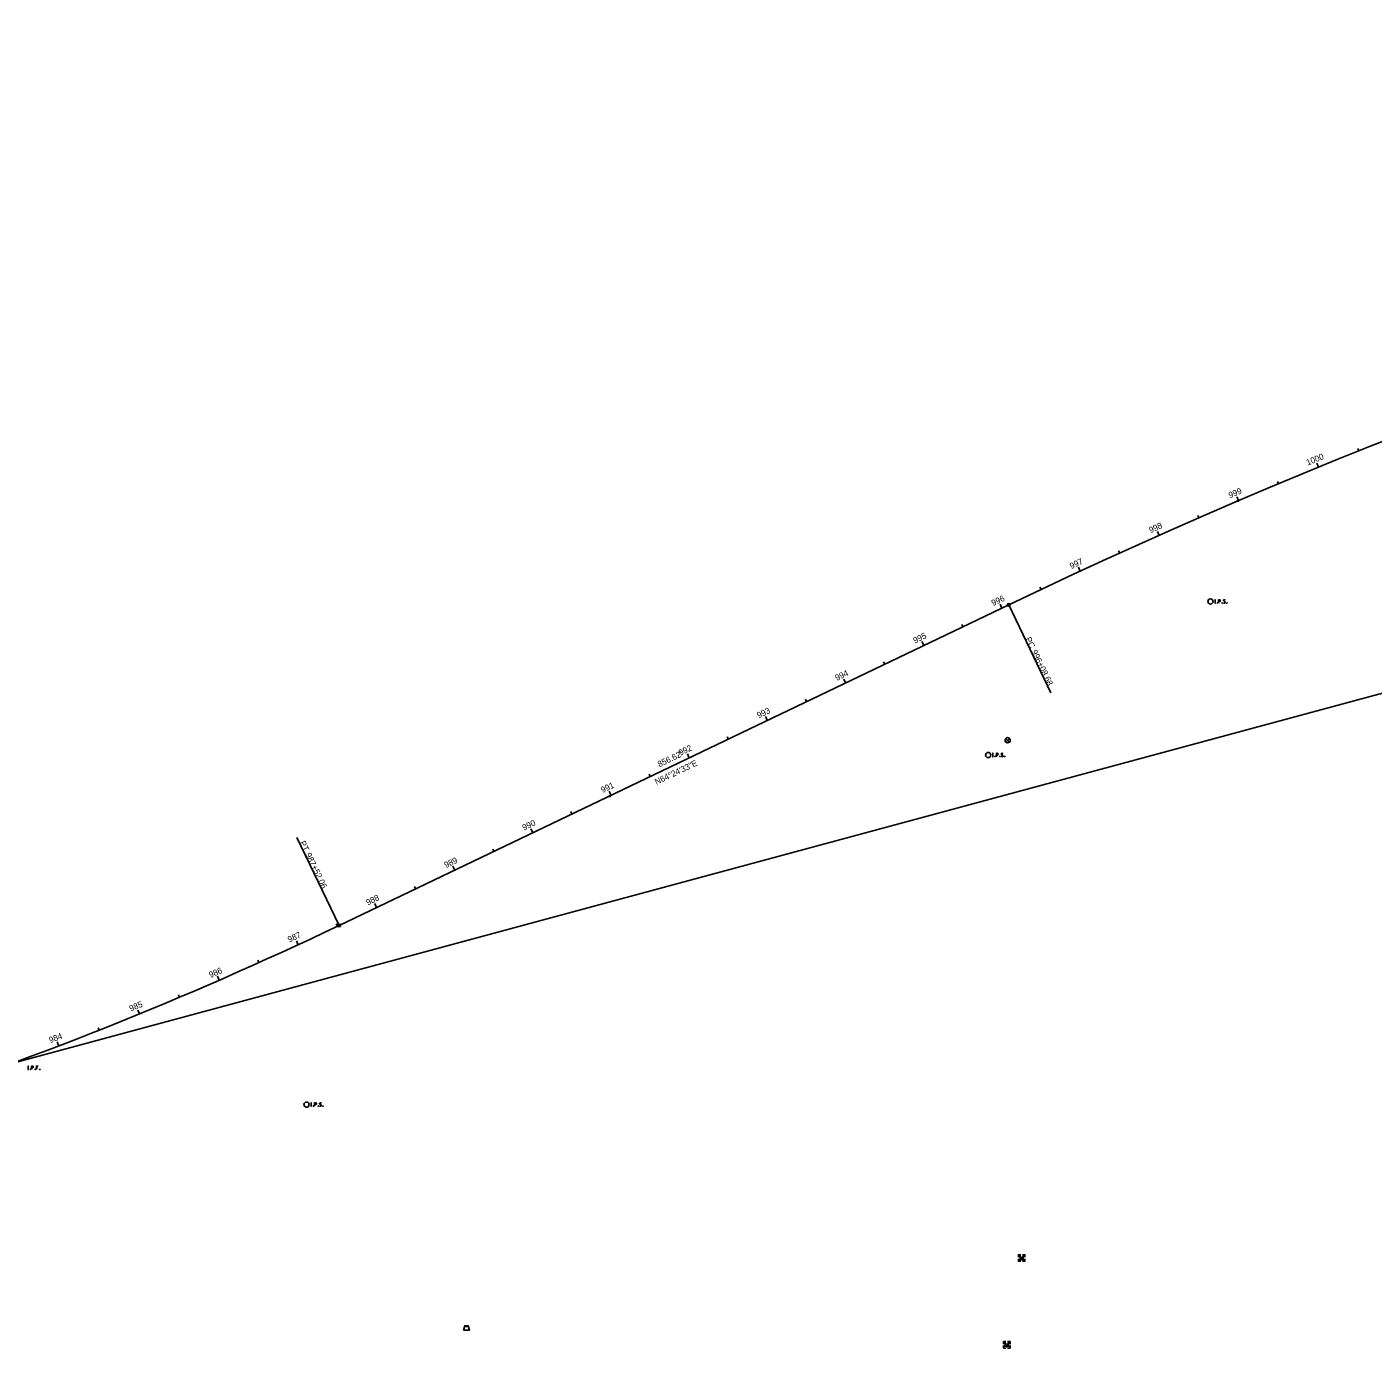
# Model space of a CAD drawing. Extents: x 2192033 to 2198234, y 657975 to 662607.
# Drawn here: x 2193587 to 2195140, y 660228 to 661753 of the extents above; entities that cross this region are included whole.
import ezdxf

# ---------------------------------------------------------------- set-up
doc = ezdxf.new("R2010")
doc.units = 0
for name, color, linetype in [('BR_P_Gen_Approach_Slab', 7, 'Continuous'), ('GE_X_Alignment_1000_Stations', 7, 'Continuous'), ('GE_X_Alignment_100_Stations', 7, 'Continuous'), ('GE_X_Alignment_500_Stations', 7, 'Continuous'), ('RD_P_Text', 7, 'Continuous'), ('SH_Border', 7, 'Continuous'), ('SH_Cut_Line', 7, 'Continuous'), ('SH_Data', 7, 'Continuous'), ('SH_Named_Boundary', 7, 'Continuous')]:
    doc.layers.add(name, color=color, linetype=linetype)

msp = doc.modelspace()

# ---------------------------------------------------------------- linework, layer by layer
at = {"layer": 'BR_P_Gen_Approach_Slab'}
for points in [[(2194957.2, 661091.7), (2194958.1, 661091.7)], [(2194957.7, 661087.7), (2194957.7, 661091.7)], [(2194961.6, 661087.7), (2194961.6, 661091.7), (2194962.9, 661091.7), (2194963, 661091.7), (2194963.2, 661091.6), (2194963.3, 661091.6), (2194963.4, 661091.5), (2194963.5, 661091.4), (2194963.6, 661091.2), (2194963.6, 661091), (2194963.6, 661090.6), (2194963.6, 661090.4), (2194963.6, 661090.3), (2194963.5, 661090), (2194963.3, 661089.9), (2194963.3, 661089.9), (2194963.1, 661089.8), (2194962.9, 661089.8), (2194961.6, 661089.8)], [(2194969.1, 661091.5), (2194969, 661091.5), (2194969, 661091.6), (2194968.7, 661091.7), (2194968.4, 661091.7), (2194968.2, 661091.7), (2194968.1, 661091.7), (2194967.8, 661091.6), (2194967.4, 661091.5), (2194967.3, 661091.2), (2194967.2, 661091), (2194967.2, 661090.8), (2194967.3, 661090.5), (2194967.5, 661090.3), (2194969, 661089.3), (2194969.1, 661089.2), (2194969.2, 661089.1), (2194969.2, 661088.9), (2194969.2, 661088.7), (2194969.2, 661088.5), (2194969.2, 661088.4), (2194969.1, 661088.2), (2194969.1, 661088.1), (2194969, 661088), (2194968.9, 661087.9), (2194968.9, 661087.9), (2194968.7, 661087.8), (2194968.7, 661087.8), (2194968.4, 661087.7), (2194968, 661087.7), (2194967.8, 661087.8), (2194967.4, 661088), (2194967.2, 661088.2)], [(2194957.2, 661087.7), (2194958.1, 661087.7)], [(2194960.1, 661088.3), (2194960.2, 661088.3), (2194960.3, 661088.2), (2194960.4, 661088.1), (2194960.4, 661087.9), (2194960.3, 661087.8), (2194960.2, 661087.7), (2194960.1, 661087.7), (2194960, 661087.8), (2194959.9, 661087.9), (2194959.9, 661088.1), (2194960, 661088.2), (2194960.1, 661088.3)], [(2194965.7, 661088.3), (2194965.8, 661088.3), (2194965.9, 661088.2), (2194966, 661088.1), (2194966, 661087.9), (2194965.9, 661087.8), (2194965.8, 661087.7), (2194965.7, 661087.7), (2194965.6, 661087.8), (2194965.5, 661087.9), (2194965.5, 661088.1), (2194965.6, 661088.2), (2194965.7, 661088.3)], [(2194971.1, 661088.3), (2194971.3, 661088.3), (2194971.4, 661088.2), (2194971.4, 661088.1), (2194971.4, 661087.9), (2194971.4, 661087.8), (2194971.3, 661087.7), (2194971.1, 661087.7), (2194971.1, 661087.8), (2194971, 661087.9), (2194971, 661088.1), (2194971.1, 661088.2), (2194971.1, 661088.3)], [(2194700.8, 660914.5), (2194701.7, 660914.5)], [(2194700.8, 660910.5), (2194701.7, 660910.5)], [(2194701.3, 660910.5), (2194701.3, 660914.5)], [(2194703.7, 660911), (2194703.8, 660911), (2194703.9, 660911), (2194704, 660910.8), (2194704, 660910.7), (2194703.9, 660910.6), (2194703.8, 660910.5), (2194703.7, 660910.5), (2194703.6, 660910.6), (2194703.5, 660910.7), (2194703.5, 660910.8), (2194703.6, 660911), (2194703.7, 660911)], [(2194705.2, 660910.5), (2194705.2, 660914.5), (2194706.5, 660914.5), (2194706.7, 660914.5), (2194706.9, 660914.4), (2194706.9, 660914.3), (2194707, 660914.3), (2194707.1, 660914.1), (2194707.2, 660914), (2194707.3, 660913.7), (2194707.3, 660913.3), (2194707.2, 660913.2), (2194707.2, 660913), (2194707.1, 660912.8), (2194707, 660912.7), (2194706.9, 660912.6), (2194706.7, 660912.6), (2194706.5, 660912.5), (2194705.2, 660912.5)], [(2194709.3, 660911), (2194709.4, 660911), (2194709.5, 660911), (2194709.6, 660910.8), (2194709.6, 660910.7), (2194709.5, 660910.6), (2194709.4, 660910.5), (2194709.3, 660910.5), (2194709.2, 660910.6), (2194709.1, 660910.7), (2194709.1, 660910.8), (2194709.2, 660911), (2194709.3, 660911)], [(2194712.7, 660914.2), (2194712.7, 660914.3), (2194712.6, 660914.3), (2194712.3, 660914.4), (2194712, 660914.5), (2194711.8, 660914.5), (2194711.7, 660914.5), (2194711.4, 660914.4), (2194711.1, 660914.2), (2194710.9, 660914), (2194710.8, 660913.7), (2194710.8, 660913.5), (2194710.9, 660913.3), (2194711.1, 660913), (2194712.6, 660912.1), (2194712.8, 660912), (2194712.8, 660911.9), (2194712.9, 660911.7), (2194712.9, 660911.5), (2194712.8, 660911.3), (2194712.8, 660911.2), (2194712.8, 660911), (2194712.7, 660910.9), (2194712.6, 660910.8), (2194712.6, 660910.7), (2194712.5, 660910.6), (2194712.4, 660910.6), (2194712.3, 660910.5), (2194712, 660910.5), (2194711.6, 660910.5), (2194711.4, 660910.6), (2194711, 660910.8), (2194710.8, 660911)], [(2194714.8, 660911), (2194714.9, 660911), (2194715, 660911), (2194715.1, 660910.8), (2194715.1, 660910.7), (2194715, 660910.6), (2194714.9, 660910.5), (2194714.8, 660910.5), (2194714.7, 660910.6), (2194714.6, 660910.7), (2194714.6, 660910.8), (2194714.7, 660911), (2194714.8, 660911)], [(2193914.4, 660511.1), (2193915.2, 660511.1)], [(2193914.4, 660507.1), (2193915.2, 660507.1)], [(2193914.8, 660507.1), (2193914.8, 660511.1)], [(2193917.2, 660507.6), (2193917.3, 660507.6), (2193917.4, 660507.5), (2193917.5, 660507.4), (2193917.5, 660507.2), (2193917.4, 660507.1), (2193917.3, 660507.1), (2193917.2, 660507.1), (2193917.1, 660507.1), (2193917, 660507.2), (2193917, 660507.4), (2193917.1, 660507.5), (2193917.2, 660507.6)], [(2193918.7, 660507.1), (2193918.7, 660511.1), (2193920, 660511.1), (2193920.2, 660511), (2193920.4, 660511), (2193920.5, 660510.9), (2193920.5, 660510.8), (2193920.6, 660510.7), (2193920.7, 660510.5), (2193920.8, 660510.3), (2193920.8, 660509.9), (2193920.8, 660509.8), (2193920.7, 660509.6), (2193920.6, 660509.4), (2193920.5, 660509.3), (2193920.4, 660509.2), (2193920.3, 660509.1), (2193920, 660509.1), (2193918.7, 660509.1)], [(2193922.8, 660507.6), (2193923, 660507.6), (2193923, 660507.5), (2193923.1, 660507.4), (2193923.1, 660507.2), (2193923, 660507.1), (2193923, 660507.1), (2193922.8, 660507.1), (2193922.7, 660507.1), (2193922.7, 660507.2), (2193922.7, 660507.4), (2193922.7, 660507.5), (2193922.8, 660507.6)], [(2193926.2, 660510.8), (2193926.2, 660510.8), (2193926.1, 660510.9), (2193925.9, 660511), (2193925.6, 660511.1), (2193925.3, 660511.1), (2193925.3, 660511.1), (2193924.9, 660511), (2193924.6, 660510.8), (2193924.4, 660510.5), (2193924.3, 660510.3), (2193924.3, 660510.1), (2193924.4, 660509.8), (2193924.6, 660509.6), (2193926.1, 660508.7), (2193926.3, 660508.5), (2193926.3, 660508.4), (2193926.4, 660508.2), (2193926.4, 660508), (2193926.4, 660507.8), (2193926.3, 660507.7), (2193926.3, 660507.6), (2193926.2, 660507.4), (2193926.2, 660507.3), (2193926.1, 660507.2), (2193926, 660507.2), (2193925.9, 660507.1), (2193925.8, 660507.1), (2193925.6, 660507.1), (2193925.2, 660507.1), (2193924.9, 660507.1), (2193924.6, 660507.3), (2193924.3, 660507.5)], [(2193928.3, 660507.6), (2193928.4, 660507.6), (2193928.5, 660507.5), (2193928.6, 660507.4), (2193928.6, 660507.2), (2193928.5, 660507.1), (2193928.4, 660507.1), (2193928.3, 660507.1), (2193928.2, 660507.1), (2193928.1, 660507.2), (2193928.1, 660507.4), (2193928.2, 660507.5), (2193928.3, 660507.6)]]:
    msp.add_lwpolyline(points, dxfattribs=at)
for centre in [(2194952.2, 661089.7), (2194695.8, 660912.5), (2193909.3, 660509)]:
    msp.add_circle(centre, 3, dxfattribs=at)
at = {"layer": 'GE_X_Alignment_1000_Stations'}
for p, q in [((2195077, 661244.7), (2195075.1, 661249.3)), ((2194719.5, 661085.8), (2194768.1, 660984.4)), ((2194621.4, 661038.9), (2194620.2, 661041.6)), ((2194170.5, 660822.9), (2194168.3, 660827.4)), ((2193946.9, 660715.8), (2193898.3, 660817.3)), ((2193716.5, 660613.6), (2193715.4, 660616.4))]:
    msp.add_line(p, q, dxfattribs=at)
for centre in [(2194719.5, 661085.8), (2193946.9, 660715.8)]:
    msp.add_circle(centre, 1.5, dxfattribs=at)
at = {"layer": 'GE_X_Alignment_100_Stations'}
for p, q in [((2195123.3, 661263.5), (2195122.2, 661266.3)), ((2195077, 661244.7), (2195075.1, 661249.3)), ((2195030.8, 661225.5), (2195029.7, 661228.3)), ((2194984.8, 661206), (2194982.8, 661210.6)), ((2194938.9, 661186.2), (2194937.7, 661189)), ((2194893.1, 661166), (2194891.1, 661170.6)), ((2194847.5, 661145.5), (2194846.3, 661148.3)), ((2194802.1, 661124.7), (2194800, 661129.3)), ((2194756.8, 661103.6), (2194755.5, 661106.3)), ((2194711.6, 661082.1), (2194709.5, 661086.6)), ((2194719.5, 661085.8), (2194768.1, 660984.4)), ((2194666.5, 661060.5), (2194665.2, 661063.2)), ((2194621.4, 661038.9), (2194619.3, 661043.4)), ((2194576.4, 661017.3), (2194575.1, 661020)), ((2194531.3, 660995.7), (2194529.1, 661000.2)), ((2194486.2, 660974.1), (2194484.9, 660976.8)), ((2194441.1, 660952.5), (2194438.9, 660957)), ((2194396, 660930.9), (2194394.7, 660933.6)), ((2194350.9, 660909.3), (2194348.7, 660913.8)), ((2194305.8, 660887.7), (2194304.5, 660890.4)), ((2194260.7, 660866.1), (2194258.5, 660870.6)), ((2194215.6, 660844.5), (2194214.3, 660847.2)), ((2194170.5, 660822.9), (2194168.3, 660827.4)), ((2193946.9, 660715.8), (2193898.3, 660817.3)), ((2194125.4, 660801.3), (2194124.1, 660804)), ((2194080.3, 660779.7), (2194078.1, 660784.2)), ((2194035.2, 660758.1), (2194033.9, 660760.8)), ((2193990.1, 660736.5), (2193988, 660741)), ((2193945, 660714.9), (2193943.7, 660717.6)), ((2193899.8, 660693.6), (2193897.7, 660698.1)), ((2193854.3, 660672.8), (2193853.1, 660675.6)), ((2193808.6, 660652.6), (2193806.6, 660657.1)), ((2193762.7, 660632.8), (2193761.5, 660635.6)), ((2193716.5, 660613.6), (2193714.6, 660618.2)), ((2193670.1, 660594.9), (2193669, 660597.7)), ((2193623.5, 660576.8), (2193621.7, 660581.5))]:
    msp.add_line(p, q, dxfattribs=at)
for centre in [(2194719.5, 661085.8), (2193946.9, 660715.8)]:
    msp.add_circle(centre, 1.5, dxfattribs=at)
at = {"layer": 'GE_X_Alignment_500_Stations'}
for p, q in [((2195077, 661244.7), (2195075.1, 661249.3)), ((2194984.8, 661206), (2194983.6, 661208.8)), ((2194893.1, 661166), (2194891.9, 661168.8)), ((2194802.1, 661124.7), (2194800.8, 661127.4)), ((2194711.6, 661082.1), (2194710.3, 661084.8)), ((2194719.5, 661085.8), (2194768.1, 660984.4)), ((2194621.4, 661038.9), (2194619.3, 661043.4)), ((2194531.3, 660995.7), (2194530, 660998.4)), ((2194441.1, 660952.5), (2194439.8, 660955.2)), ((2194350.9, 660909.3), (2194349.6, 660912)), ((2194260.7, 660866.1), (2194259.4, 660868.8)), ((2194170.5, 660822.9), (2194168.3, 660827.4)), ((2193946.9, 660715.8), (2193898.3, 660817.3)), ((2194080.3, 660779.7), (2194079, 660782.4)), ((2193990.1, 660736.5), (2193988.8, 660739.2)), ((2193899.8, 660693.6), (2193898.5, 660696.3)), ((2193808.6, 660652.6), (2193807.4, 660655.3)), ((2193716.5, 660613.6), (2193714.6, 660618.2)), ((2193623.5, 660576.8), (2193622.5, 660579.6))]:
    msp.add_line(p, q, dxfattribs=at)
for centre in [(2194719.5, 661085.8), (2193946.9, 660715.8)]:
    msp.add_circle(centre, 1.5, dxfattribs=at)
at = {"layer": 'RD_P_Text'}
msp.add_line((2193946.9, 660715.8), (2194719.5, 661085.8), dxfattribs=at)
for centre, radius, start, end in [((2197687.9, 654887.7), 6872.3, 93.57492, 115.59076), ((2192075.3, 664623.8), 4333, 280.0763, 295.5908)]:
    msp.add_arc(centre, radius, start, end, dxfattribs=at)
at = {"layer": 'SH_Border'}
msp.add_line((2192833.4, 660357.6), (2197996.1, 661752.8), dxfattribs=at)
at = {"layer": 'SH_Cut_Line'}
for p, q in [((2194720.3, 660927.5), (2194716, 660931.7)), ((2194716, 660927.5), (2194720.3, 660931.7))]:
    msp.add_line(p, q, dxfattribs=at)
msp.add_circle((2194718.2, 660929.6), 3, dxfattribs=at)
at = {"layer": 'SH_Data'}
for p, q in [((2194982.8, 661206), (2194985.3, 661206)), ((2194984, 661207.2), (2194984, 661204.7)), ((2194984, 661206), (2194984, 661206)), ((2194257.9, 660865.1), (2194260.4, 660865.1)), ((2194259.1, 660866.3), (2194259.1, 660863.8)), ((2194259.1, 660865.1), (2194259.1, 660865.1))]:
    msp.add_line(p, q, dxfattribs=at)
at = {"layer": 'SH_Named_Boundary'}
for p, q in [((2194734.4, 660332.1), (2194734.4, 660332.1)), ((2194093.9, 660253.7), (2194093.9, 660252.2)), ((2194717.3, 660231.8), (2194717.3, 660231.8))]:
    msp.add_line(p, q, dxfattribs=at)
for points in [[(2193587.7, 660553.5), (2193588.6, 660553.5)], [(2193587.7, 660549.5), (2193588.6, 660549.5)], [(2193588.2, 660549.5), (2193588.2, 660553.5)], [(2193590.6, 660550.1), (2193590.7, 660550.1), (2193590.8, 660550), (2193590.9, 660549.9), (2193590.9, 660549.7), (2193590.8, 660549.6), (2193590.7, 660549.5), (2193590.6, 660549.5), (2193590.5, 660549.6), (2193590.4, 660549.7), (2193590.4, 660549.9), (2193590.5, 660550), (2193590.6, 660550.1)], [(2193592.1, 660549.5), (2193592.1, 660553.5), (2193593.4, 660553.5), (2193593.6, 660553.5), (2193593.8, 660553.4), (2193593.8, 660553.4), (2193593.9, 660553.3), (2193594, 660553.2), (2193594.1, 660553), (2193594.2, 660552.8), (2193594.2, 660552.4), (2193594.1, 660552.3), (2193594.1, 660552.1), (2193594, 660551.8), (2193593.9, 660551.7), (2193593.8, 660551.7), (2193593.6, 660551.6), (2193593.4, 660551.6), (2193592.1, 660551.6)], [(2193596.2, 660550.1), (2193596.3, 660550.1), (2193596.4, 660550), (2193596.5, 660549.9), (2193596.5, 660549.7), (2193596.4, 660549.6), (2193596.3, 660549.5), (2193596.2, 660549.5), (2193596.1, 660549.6), (2193596, 660549.7), (2193596, 660549.9), (2193596.1, 660550), (2193596.2, 660550.1)], [(2193599.6, 660553.5), (2193597.7, 660553.5), (2193597.7, 660549.5)], [(2193597.7, 660551.6), (2193599.1, 660551.6)], [(2193601.6, 660550.1), (2193601.7, 660550.1), (2193601.8, 660550), (2193601.9, 660549.9), (2193601.9, 660549.7), (2193601.8, 660549.6), (2193601.7, 660549.5), (2193601.6, 660549.5), (2193601.5, 660549.6), (2193601.4, 660549.7), (2193601.4, 660549.9), (2193601.5, 660550), (2193601.6, 660550.1)], [(2194730.7, 660333), (2194730.7, 660335.8), (2194733.5, 660335.8)], [(2194733.5, 660328.3), (2194730.7, 660328.3), (2194730.7, 660331.1)], [(2194732.6, 660329.6), (2194732.6, 660334.6), (2194734.4, 660329.6), (2194736.3, 660334.6), (2194736.3, 660329.6)], [(2194735.3, 660335.8), (2194738.2, 660335.8), (2194738.2, 660333)], [(2194738.2, 660331.1), (2194738.2, 660328.3), (2194735.3, 660328.3)], [(2194713.5, 660232.7), (2194713.5, 660235.5), (2194716.3, 660235.5)], [(2194716.3, 660228), (2194713.5, 660228), (2194713.5, 660230.8)], [(2194715.4, 660229.3), (2194715.4, 660234.3), (2194717.3, 660229.3), (2194719.1, 660234.3), (2194719.1, 660229.3)], [(2194718.2, 660235.5), (2194721, 660235.5), (2194721, 660232.7)], [(2194721, 660230.8), (2194721, 660228), (2194718.2, 660228)]]:
    msp.add_lwpolyline(points, dxfattribs=at)
msp.add_lwpolyline([(2194090.4, 660248.7), (2194097.4, 660248.7), (2194095.9, 660253.7), (2194091.9, 660253.7)], close=True, dxfattribs=at)

# ---------------------------------------------------------------- texts
at = {"layer": 'GE_X_Alignment_1000_Stations'}
for s, rotation, p in [('1000', 22.3283, (2195064.5, 661246.5)), ('PC', 295.5908, (2194738.4, 661046.6)), ('996+08.68', 295.5908, (2194745.4, 661031.9)), ('N64°24\'33"E', 25.5908, (2194313.1, 660877.9)), ("856.62'", 25.5908, (2194316.4, 660898.3)), ('990', 25.5908, (2194160.3, 660825.1)), ('PT', 295.5908, (2193901.2, 660811.4)), ('987+52.06', 295.5908, (2193907.8, 660797.7))]:
    msp.add_text(s, height=7, rotation=rotation, dxfattribs=at).set_placement(p)
at = {"layer": 'GE_X_Alignment_100_Stations'}
for s, rotation, p in [('1000', 22.3283, (2195064.5, 661246.5)), ('999', 23.162, (2194974.8, 661208.7)), ('998', 23.9957, (2194883.1, 661168.5)), ('997', 24.8294, (2194791.8, 661127)), ('996', 25.5908, (2194701.5, 661084.3)), ('995', 25.5908, (2194611.3, 661041.1)), ('PC', 295.5908, (2194738.4, 661046.6)), ('996+08.68', 295.5908, (2194745.4, 661031.9)), ('994', 25.5908, (2194521.2, 660997.9)), ('993', 25.5908, (2194431, 660954.7)), ('992', 25.5908, (2194340.7, 660911.5)), ('N64°24\'33"E', 25.5908, (2194313.1, 660877.9)), ('991', 25.5908, (2194250.9, 660868.5)), ('990', 25.5908, (2194160.3, 660825.1)), ('PT', 295.5908, (2193901.2, 660811.4)), ('987+52.06', 295.5908, (2193907.8, 660797.7)), ('989', 25.5908, (2194070.2, 660781.9)), ('988', 25.5908, (2193980, 660738.7)), ('987', 24.9023, (2193889.5, 660695.9)), ('986', 23.58, (2193798.5, 660655.1)), ('985', 22.2577, (2193706.5, 660616.4)), ('984', 20.9354, (2193613.7, 660579.9))]:
    msp.add_text(s, height=7, rotation=rotation, dxfattribs=at).set_placement(p)
at = {"layer": 'GE_X_Alignment_500_Stations'}
for s, rotation, p in [('1000', 22.3283, (2195064.5, 661246.5)), ('995', 25.5908, (2194611.3, 661041.1)), ('PC', 295.5908, (2194738.4, 661046.6)), ('996+08.68', 295.5908, (2194745.4, 661031.9)), ('N64°24\'33"E', 25.5908, (2194313.1, 660877.9)), ("856.62'", 25.5908, (2194316.4, 660898.3)), ('990', 25.5908, (2194160.3, 660825.1)), ('PT', 295.5908, (2193901.2, 660811.4)), ('987+52.06', 295.5908, (2193907.8, 660797.7)), ('985', 22.2577, (2193706.5, 660616.4))]:
    msp.add_text(s, height=7, rotation=rotation, dxfattribs=at).set_placement(p)

doc.saveas('drawing.dxf')
